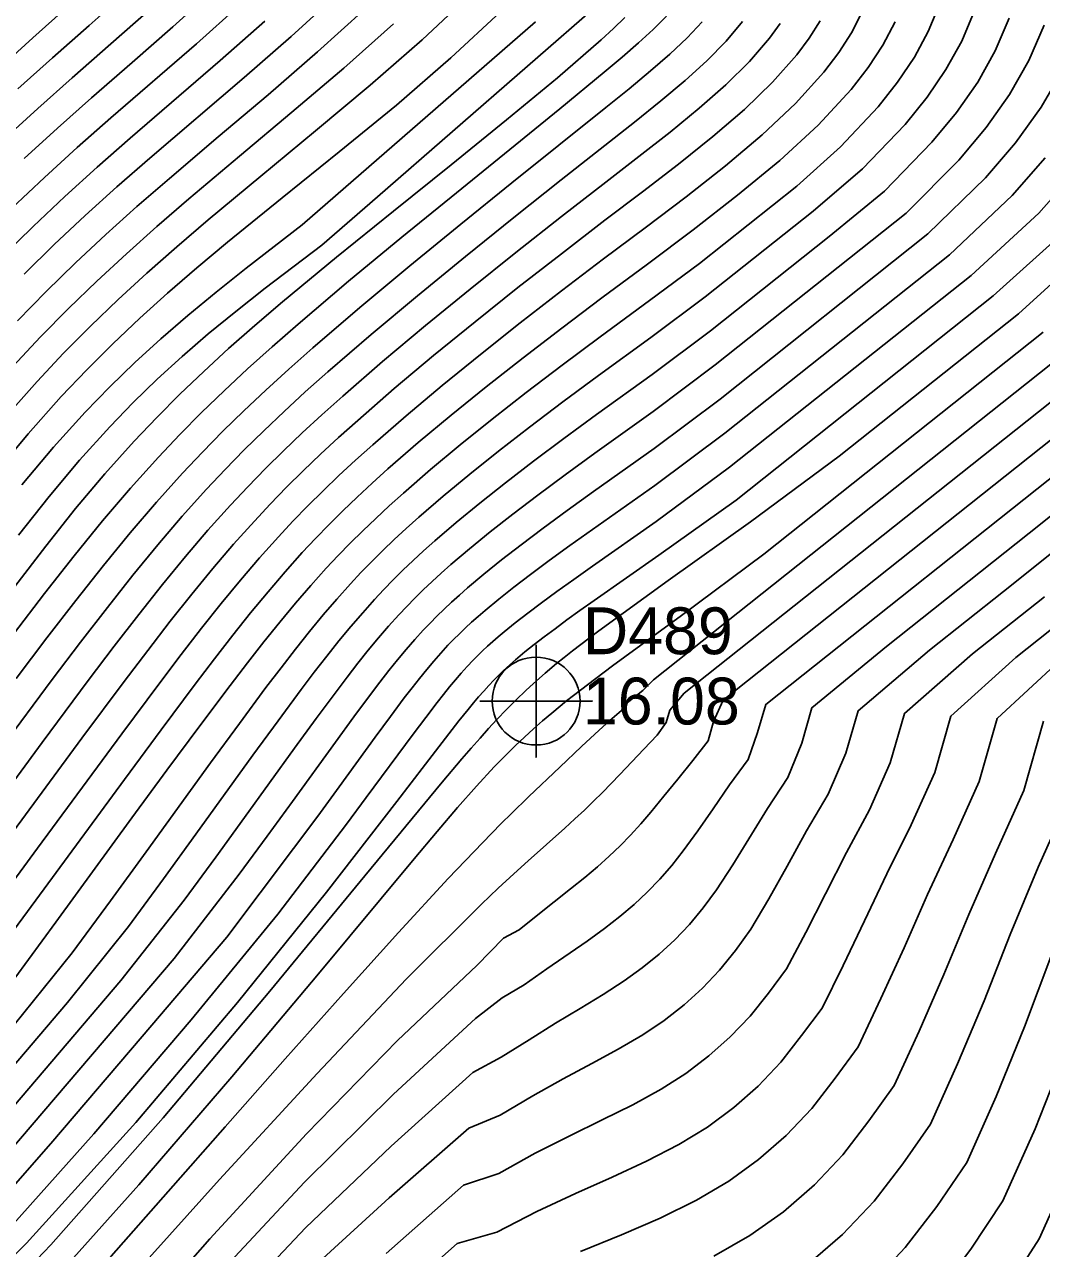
# Model space of a CAD drawing. Extents: x 2356077 to 2359823, y 225951 to 227822.
# Drawn here: x 2356793.7 to 2356848, y 226873.7 to 226939 of the extents above; entities that cross this region are included whole.
import ezdxf

# ---------------------------------------------------------------- set-up
doc = ezdxf.new("R2010")
doc.units = 0
for name, color, linetype in [('DTM Contours Major', 7, 'Continuous'), ('DTM Contours Minor', 7, 'Continuous'), ('Exist DTM Regular Point CELL', 7, 'Continuous'), ('Exist DTM Regular Point Cogo Elevation', 7, 'Continuous'), ('Exist DTM Regular Point Cogo Number', 7, 'Continuous')]:
    doc.layers.add(name, color=color, linetype=linetype)

msp = doc.modelspace()

# ---------------------------------------------------------------- linework, layer by layer
at = {"layer": 'DTM Contours Major'}
for points in [[(2356796.008, 226939.965), (2356794.163, 226938.318), (2356792.307, 226936.646)], [(2356819.099, 226939.709), (2356816.463, 226937.248), (2356813.552, 226934.723), (2356810.505, 226932.227), (2356807.458, 226929.779), (2356804.549, 226927.417), (2356802.905, 226926.041), (2356801.347, 226924.691), (2356799.86, 226923.348), (2356798.429, 226921.993), (2356797.038, 226920.607), (2356795.674, 226919.171), (2356793.902, 226917.187), (2356792.128, 226915.072)], [(2356840.15, 226939.164), (2356839.498, 226937.933), (2356838.717, 226936.738), (2356837.807, 226935.565), (2356836.043, 226933.657), (2356834.006, 226931.772), (2356831.757, 226929.917), (2356829.389, 226928.066), (2356826.949, 226926.245), (2356824.517, 226924.443), (2356822.374, 226922.831), (2356820.308, 226921.243), (2356818.334, 226919.689), (2356816.466, 226918.176), (2356814.717, 226916.713), (2356813.104, 226915.31), (2356812.265, 226914.554), (2356811.465, 226913.812), (2356810.699, 226913.077), (2356809.96, 226912.342), (2356809.241, 226911.6), (2356808.534, 226910.845), (2356807.619, 226909.823), (2356806.704, 226908.756), (2356805.778, 226907.633), (2356804.83, 226906.444), (2356803.848, 226905.179), (2356802.821, 226903.829), (2356801.004, 226901.393), (2356799.048, 226898.734), (2356794.772, 226892.901), (2356792.48, 226889.804)], [(2356806.539, 226939.206), (2356804.161, 226937.103), (2356799.36, 226932.968), (2356797.585, 226931.405), (2356795.859, 226929.84), (2356794.172, 226928.253), (2356792.515, 226926.624)], [(2356829.864, 226939.174), (2356829.058, 226938.318), (2356828.136, 226937.446), (2356827.104, 226936.546), (2356825.966, 226935.602), (2356824.728, 226934.6), (2356819.717, 226930.576), (2356816.998, 226928.38), (2356814.261, 226926.14), (2356811.598, 226923.919), (2356809.101, 226921.776), (2356807.808, 226920.632), (2356806.585, 226919.518), (2356805.418, 226918.419), (2356804.295, 226917.322), (2356803.206, 226916.213), (2356802.137, 226915.079), (2356800.748, 226913.532), (2356799.352, 226911.899), (2356797.929, 226910.16), (2356796.456, 226908.296), (2356794.913, 226906.289), (2356793.279, 226904.119)], [(2356849.089, 226936.576), (2356847.954, 226934.622), (2356846.582, 226932.721), (2356844.98, 226930.844), (2356841.902, 226927.85), (2356830.816, 226919.04), (2356827.299, 226916.396), (2356824.07, 226914.101), (2356822.661, 226913.085), (2356821.378, 226912.143), (2356820.215, 226911.268), (2356819.162, 226910.453), (2356818.211, 226909.689), (2356817.353, 226908.968), (2356816.912, 226908.582), (2356816.494, 226908.203), (2356816.095, 226907.83), (2356815.714, 226907.458), (2356815.346, 226907.085), (2356814.987, 226906.708), (2356814.528, 226906.202), (2356814.073, 226905.678), (2356813.617, 226905.129), (2356813.152, 226904.549), (2356812.673, 226903.932), (2356812.173, 226903.273), (2356811.283, 226902.074), (2356810.303, 226900.731), (2356808.009, 226897.565), (2356806.667, 226895.72), (2356805.173, 226893.685), (2356801.698, 226889.177), (2356792.882, 226878.843)], [(2356848.045, 226922.603), (2356833.152, 226910.767), (2356828.768, 226907.493), (2356825.081, 226904.806), (2356824.184, 226904.134), (2356823.371, 226903.511), (2356822.634, 226902.929), (2356821.839, 226902.281), (2356821.347, 226901.864), (2356820.864, 226901.441), (2356820.384, 226901.003), (2356819.912, 226900.556), (2356819.677, 226900.326), (2356818.773, 226899.405), (2356817.83, 226898.384), (2356816.821, 226897.243), (2356815.722, 226895.959), (2356814.505, 226894.512), (2356809.307, 226888.259), (2356804.777, 226882.869), (2356799.811, 226877.101), (2356794.662, 226871.347), (2356789.585, 226866.001)], [(2356852.128, 226915.737), (2356847.915, 226912.369), (2356839.688, 226905.831), (2356835.712, 226902.565), (2356835.174, 226900.676), (2356834.434, 226898.85), (2356833.356, 226897.194), (2356831.506, 226894.176), (2356830.633, 226892.844), (2356829.924, 226891.885), (2356829.184, 226891.001), (2356828.402, 226890.181), (2356827.567, 226889.413), (2356826.668, 226888.686), (2356825.694, 226887.988), (2356824.576, 226887.266), (2356823.361, 226886.526), (2356822.045, 226885.733), (2356820.628, 226884.848), (2356819.137, 226883.924), (2356817.636, 226883.101), (2356813.282, 226879.173), (2356808.71, 226874.817), (2356803.985, 226869.818)], [(2356848.073, 226901.855), (2356847.017, 226898.148), (2356845.511, 226894.788), (2356844.083, 226891.527), (2356842.758, 226888.337), (2356841.435, 226885.302), (2356840.111, 226882.402), (2356838.752, 226880.515), (2356837.365, 226878.717), (2356835.847, 226877.105), (2356834.197, 226875.67), (2356832.412, 226874.403), (2356830.492, 226873.294)]]:
    msp.add_lwpolyline(points, dxfattribs=at)
at = {"layer": 'DTM Contours Minor'}
for points in [[(2356817.46, 226940.6), (2356814.935, 226938.214), (2356812.156, 226935.783), (2356809.246, 226933.346), (2356806.326, 226930.94), (2356803.519, 226928.604), (2356801.844, 226927.17), (2356800.249, 226925.761), (2356798.72, 226924.356), (2356797.242, 226922.937), (2356795.803, 226921.484), (2356794.386, 226919.978), (2356792.543, 226917.899)], [(2356799.09, 226940.699), (2356797.163, 226938.976), (2356795.208, 226937.248), (2356793.365, 226935.597)], [(2356803.75, 226940.822), (2356801.629, 226938.901), (2356799.461, 226937.001), (2356797.29, 226935.11), (2356795.477, 226933.502), (2356793.69, 226931.873)], [(2356810.339, 226940.596), (2356807.942, 226938.391), (2356805.433, 226936.198), (2356800.402, 226931.894), (2356798.649, 226930.358), (2356796.953, 226928.827), (2356795.305, 226927.282), (2356793.693, 226925.705)], [(2356805.144, 226940.015), (2356802.896, 226938.003), (2356798.327, 226934.04), (2356796.532, 226932.455), (2356794.775, 226930.857), (2356793.047, 226929.228)], [(2356842.515, 226940.09), (2356841.924, 226938.656), (2356841.182, 226937.279), (2356840.289, 226935.942), (2356839.248, 226934.63), (2356837.235, 226932.492), (2356834.911, 226930.398), (2356829.729, 226926.28), (2356827.052, 226924.291), (2356824.426, 226922.364), (2356822.398, 226920.852), (2356820.474, 226919.385), (2356818.658, 226917.965), (2356816.957, 226916.595), (2356815.377, 226915.279), (2356813.924, 226914.018), (2356813.169, 226913.339), (2356812.45, 226912.672), (2356811.76, 226912.011), (2356811.094, 226911.351), (2356810.446, 226910.685), (2356809.811, 226910.008), (2356808.988, 226909.094), (2356808.165, 226908.141), (2356807.334, 226907.14), (2356806.484, 226906.082), (2356805.605, 226904.959), (2356804.687, 226903.762), (2356803.065, 226901.604), (2356801.316, 226899.239), (2356799.448, 226896.689), (2356795.378, 226891.117), (2356793.191, 226888.137)], [(2356811.869, 226939.845), (2356809.346, 226937.562), (2356806.705, 226935.281), (2356804.039, 226933.025), (2356801.441, 226930.815), (2356799.712, 226929.307), (2356798.049, 226927.813), (2356796.439, 226926.312), (2356794.872, 226924.785), (2356793.334, 226923.214)], [(2356824.551, 226940.282), (2356812.545, 226929.831), (2356809.572, 226927.246), (2356806.546, 226924.949), (2356804.988, 226923.719), (2356803.521, 226922.512), (2356802.13, 226921.311), (2356800.8, 226920.098), (2356799.517, 226918.855), (2356798.265, 226917.564), (2356796.648, 226915.772), (2356795.034, 226913.848), (2356793.398, 226911.77)], [(2356846.233, 226939.364), (2356845.496, 226937.626), (2356844.562, 226935.957), (2356843.435, 226934.337), (2356842.121, 226932.742), (2356839.581, 226930.135), (2356836.633, 226927.715), (2356830.301, 226922.682), (2356827.199, 226920.352), (2356824.234, 226918.214), (2356822.484, 226916.931), (2356820.864, 226915.718), (2356819.37, 226914.57), (2356817.997, 226913.482), (2356816.741, 226912.448), (2356815.596, 226911.465), (2356815.004, 226910.936), (2356814.441, 226910.416), (2356813.902, 226909.901), (2356813.383, 226909.388), (2356812.88, 226908.871), (2356812.389, 226908.346), (2356811.754, 226907.64), (2356811.123, 226906.905), (2356810.488, 226906.135), (2356809.84, 226905.323), (2356809.172, 226904.46), (2356808.475, 226903.539), (2356807.242, 226901.876), (2356805.9, 226900.034), (2356802.852, 226895.819), (2356801.129, 226893.445), (2356799.261, 226890.892), (2356796.006, 226886.832), (2356788.454, 226877.979)], [(2356836.152, 226939.222), (2356835.579, 226938.305), (2356834.914, 226937.406), (2356833.622, 226935.944), (2356832.115, 226934.494), (2356830.43, 226933.043), (2356828.603, 226931.581), (2356826.672, 226930.096), (2356824.674, 226928.578), (2356822.355, 226926.797), (2356820.035, 226924.984), (2356817.75, 226923.163), (2356815.539, 226921.358), (2356813.439, 226919.595), (2356811.487, 226917.899), (2356810.473, 226916.988), (2356809.508, 226916.095), (2356808.585, 226915.213), (2356807.694, 226914.331), (2356806.828, 226913.439), (2356805.977, 226912.53), (2356804.872, 226911.296), (2356803.765, 226910.001), (2356802.642, 226908.634), (2356801.487, 226907.18), (2356800.286, 226905.627), (2356799.025, 226903.962), (2356796.782, 226900.951), (2356791.835, 226894.241)], [(2356838.385, 226939.668), (2356837.821, 226938.581), (2356837.147, 226937.526), (2356836.362, 226936.491), (2356834.84, 226934.81), (2356833.073, 226933.144), (2356831.113, 226931.489), (2356829.012, 226929.837), (2356826.825, 226928.181), (2356824.601, 226926.515), (2356822.361, 226924.814), (2356820.163, 226923.11), (2356818.033, 226921.422), (2356815.994, 226919.764), (2356814.072, 226918.152), (2356812.292, 226916.604), (2356811.366, 226915.77), (2356810.485, 226914.953), (2356809.641, 226914.144), (2356808.827, 226913.335), (2356808.034, 226912.519), (2356807.256, 226911.686), (2356806.246, 226910.558), (2356805.235, 226909.377), (2356804.211, 226908.131), (2356803.16, 226906.81), (2356802.07, 226905.403), (2356800.928, 226903.897), (2356798.902, 226901.178), (2356794.417, 226895.079), (2356792.006, 226891.818)], [(2356832.008, 226939.181), (2356831.138, 226938.136), (2356830.114, 226937.093), (2356828.95, 226936.036), (2356827.659, 226934.951), (2356826.254, 226933.822), (2356822.345, 226930.74), (2356819.817, 226928.73), (2356817.237, 226926.652), (2356814.675, 226924.554), (2356812.203, 226922.484), (2356809.892, 226920.489), (2356808.694, 226919.421), (2356807.558, 226918.379), (2356806.474, 226917.351), (2356805.429, 226916.325), (2356804.414, 226915.287), (2356803.417, 226914.227), (2356802.123, 226912.783), (2356800.823, 226911.263), (2356799.5, 226909.648), (2356798.134, 226907.923), (2356796.707, 226906.071), (2356795.198, 226904.075), (2356792.503, 226900.448)], [(2356800.361, 226939.799), (2356798.314, 226937.988), (2356796.251, 226936.179), (2356794.421, 226934.55), (2356792.605, 226932.888)], [(2356827.953, 226939.467), (2356827.255, 226938.767), (2356826.471, 226938.043), (2356825.6, 226937.284), (2356824.643, 226936.476), (2356822.271, 226934.522), (2356819.604, 226932.357), (2356816.757, 226930.053), (2356813.847, 226927.683), (2356810.992, 226925.322), (2356808.306, 226923.043), (2356806.918, 226921.827), (2356805.607, 226920.645), (2356804.358, 226919.48), (2356803.158, 226918.317), (2356801.995, 226917.14), (2356800.854, 226915.934), (2356799.372, 226914.286), (2356797.882, 226912.54), (2356796.361, 226910.675), (2356794.785, 226908.668), (2356793.13, 226906.5)], [(2356844.37, 226939.729), (2356843.707, 226938.143), (2356842.87, 226936.62), (2356841.862, 226935.142), (2356840.686, 226933.688), (2356838.413, 226931.317), (2356835.778, 226929.061), (2356830.024, 226924.489), (2356827.133, 226922.326), (2356824.328, 226920.288), (2356822.432, 226918.886), (2356820.656, 226917.544), (2356819, 226916.26), (2356817.464, 226915.032), (2356816.048, 226913.859), (2356814.752, 226912.739), (2356814.08, 226912.135), (2356813.439, 226911.542), (2356812.826, 226910.954), (2356812.235, 226910.367), (2356811.661, 226909.776), (2356811.099, 226909.174), (2356810.371, 226908.363), (2356809.647, 226907.519), (2356808.916, 226906.633), (2356808.17, 226905.697), (2356807.4, 226904.704), (2356806.597, 226903.644), (2356805.178, 226901.733), (2356803.641, 226899.628), (2356800.203, 226894.881), (2356798.297, 226892.257), (2356796.261, 226889.481), (2356793.156, 226885.654)], [(2356825.735, 226939.396), (2356825.129, 226938.81), (2356824.473, 226938.212), (2356822.149, 226936.188), (2356819.435, 226933.936), (2356816.471, 226931.541), (2356813.396, 226929.072), (2356810.351, 226926.61), (2356807.481, 226924.232), (2356805.999, 226922.965), (2356804.602, 226921.731), (2356803.274, 226920.514), (2356802.001, 226919.296), (2356800.77, 226918.06), (2356799.565, 226916.79), (2356798.004, 226915.047), (2356796.439, 226913.191), (2356794.846, 226911.198), (2356793.198, 226909.045)], [(2356820.979, 226939.176), (2356808.524, 226928.333), (2356805.546, 226926.027), (2356803.94, 226924.749), (2356802.425, 226923.496), (2356800.984, 226922.247), (2356799.603, 226920.984), (2356798.265, 226919.688), (2356796.957, 226918.34), (2356795.261, 226916.469), (2356793.564, 226914.461)], [(2356848.104, 226938.994), (2356847.29, 226937.103), (2356846.257, 226935.291), (2356845.009, 226933.53), (2356843.552, 226931.794), (2356840.739, 226928.952), (2356830.563, 226920.865), (2356827.253, 226918.374), (2356824.145, 226916.149), (2356822.558, 226914.994), (2356821.102, 226913.915), (2356819.772, 226912.903), (2356818.56, 226911.952), (2356817.458, 226911.055), (2356816.46, 226910.206), (2356815.945, 226909.749), (2356815.456, 226909.301), (2356814.989, 226908.858), (2356814.541, 226908.417), (2356814.107, 226907.973), (2356813.684, 226907.524), (2356813.139, 226906.92), (2356812.599, 226906.293), (2356812.055, 226905.635), (2356811.502, 226904.942), (2356810.931, 226904.205), (2356810.335, 226903.418), (2356809.279, 226901.993), (2356808.122, 226900.405), (2356805.455, 226896.717), (2356803.919, 226894.601), (2356802.232, 226892.296), (2356798.855, 226888.008), (2356790.661, 226878.403)], [(2356834.016, 226939.072), (2356833.462, 226938.304), (2356832.389, 226937.056), (2356831.131, 226935.813), (2356829.711, 226934.562), (2356828.155, 226933.289), (2356826.485, 226931.98), (2356824.726, 226930.622), (2356822.352, 226928.776), (2356819.921, 226926.86), (2356817.486, 226924.908), (2356815.1, 226922.957), (2356812.816, 226921.04), (2356810.687, 226919.195), (2356809.582, 226918.205), (2356808.533, 226917.238), (2356807.529, 226916.282), (2356806.562, 226915.327), (2356805.621, 226914.362), (2356804.697, 226913.377), (2356803.498, 226912.038), (2356802.295, 226910.63), (2356801.072, 226909.139), (2356799.812, 226907.551), (2356798.498, 226905.85), (2356797.115, 226904.021), (2356794.649, 226900.708), (2356792.002, 226897.121)], [(2356813.402, 226939.062), (2356810.751, 226936.703), (2356807.976, 226934.34), (2356805.184, 226932.003), (2356802.481, 226929.723), (2356800.778, 226928.249), (2356799.148, 226926.793), (2356797.578, 226925.338), (2356796.056, 226923.864), (2356794.567, 226922.351), (2356793.099, 226920.78)], [(2356848.156, 226931.912), (2356846.404, 226929.895), (2356843.058, 226926.743), (2356831.065, 226917.212), (2356827.346, 226914.432), (2356824.019, 226912.084), (2356822.806, 226911.217), (2356821.706, 226910.418), (2356820.713, 226909.682), (2356819.818, 226908.999), (2356819.013, 226908.362), (2356818.289, 226907.764), (2356817.917, 226907.444), (2356817.565, 226907.131), (2356817.231, 226906.823), (2356816.911, 226906.517), (2356816.603, 226906.21), (2356816.304, 226905.9), (2356815.922, 226905.486), (2356815.545, 226905.057), (2356815.168, 226904.608), (2356814.784, 226904.133), (2356814.388, 226903.628), (2356813.975, 226903.088), (2356813.239, 226902.103), (2356812.424, 226900.992), (2356810.497, 226898.346), (2356809.355, 226896.785), (2356808.073, 226895.048), (2356804.513, 226890.332), (2356799.995, 226885.017), (2356795.128, 226879.312), (2356790.232, 226873.745)], [(2356849.731, 226931.107), (2356847.83, 226928.954), (2356844.213, 226925.635), (2356831.329, 226915.396), (2356827.412, 226912.507), (2356824.015, 226910.125), (2356823.017, 226909.418), (2356822.113, 226908.769), (2356821.295, 226908.17), (2356820.557, 226907.615), (2356819.892, 226907.099), (2356819.293, 226906.613), (2356818.985, 226906.353), (2356818.692, 226906.099), (2356818.414, 226905.849), (2356818.148, 226905.6), (2356817.892, 226905.351), (2356817.643, 226905.101), (2356817.326, 226904.766), (2356817.013, 226904.42), (2356816.701, 226904.059), (2356816.385, 226903.677), (2356816.06, 226903.272), (2356815.722, 226902.839), (2356815.12, 226902.05), (2356814.456, 226901.16), (2356811.949, 226897.769), (2356810.898, 226896.36), (2356807.237, 226891.557), (2356802.611, 226885.92), (2356797.421, 226879.837), (2356792.073, 226873.862)], [(2356849.274, 226928.047), (2356845.385, 226924.54), (2356831.683, 226913.651), (2356827.559, 226910.705), (2356824.104, 226908.287), (2356823.345, 226907.749), (2356822.65, 226907.25), (2356822.014, 226906.785), (2356821.431, 226906.349), (2356820.898, 226905.938), (2356820.41, 226905.547), (2356819.911, 226905.127), (2356819.451, 226904.717), (2356819.232, 226904.512), (2356819.019, 226904.306), (2356818.746, 226904.031), (2356818.477, 226903.748), (2356818.209, 226903.455), (2356817.939, 226903.148), (2356817.663, 226902.824), (2356817.379, 226902.481), (2356816.881, 226901.864), (2356816.343, 226901.177), (2356815.101, 226899.562), (2356813.579, 226897.57), (2356809.82, 226892.732), (2356805.084, 226886.844), (2356799.658, 226880.426), (2356793.829, 226873.996), (2356787.884, 226868.072)], [(2356850.871, 226927.334), (2356846.744, 226923.595), (2356837.167, 226915.984), (2356832.437, 226912.483), (2356828.05, 226909.361), (2356824.353, 226906.678), (2356823.39, 226905.948), (2356822.941, 226905.598), (2356822.511, 226905.256), (2356822.098, 226904.921), (2356821.485, 226904.406), (2356820.861, 226903.857), (2356820.46, 226903.487), (2356819.942, 226902.991), (2356819.428, 226902.475), (2356818.908, 226901.931), (2356818.468, 226901.454), (2356818.014, 226900.95), (2356817.543, 226900.415), (2356817.051, 226899.846), (2356815.993, 226898.598), (2356811.861, 226893.596), (2356806.793, 226887.439), (2356801.105, 226880.688), (2356795.112, 226873.903), (2356789.133, 226867.643)], [(2356849.755, 226921.935), (2356827.267, 226904.064), (2356826.691, 226903.493), (2356825.703, 226902.713), (2356825.556, 226902.425), (2356824.94, 226901.879), (2356824.369, 226901.362), (2356823.427, 226900.494), (2356822.264, 226899.404), (2356820.616, 226897.834), (2356819.67, 226896.912), (2356819.161, 226896.406), (2356818.624, 226895.862), (2356816.323, 226893.453), (2356813.662, 226890.566), (2356810.73, 226887.318), (2356807.617, 226883.825), (2356804.411, 226880.2), (2356798.33, 226873.306), (2356795.536, 226870.162), (2356792.827, 226867.155)], [(2356851.335, 226921.165), (2356828.908, 226903.342), (2356828.138, 226902.442), (2356827.949, 226901.779), (2356827.463, 226901.11), (2356826.749, 226900.364), (2356825.478, 226899.01), (2356825.006, 226898.518), (2356824.539, 226898.043), (2356824.067, 226897.575), (2356823.583, 226897.108), (2356823.077, 226896.634), (2356822.542, 226896.143), (2356820.577, 226894.39), (2356819.813, 226893.699), (2356818.985, 226892.935), (2356818.088, 226892.087), (2356814.079, 226888.076), (2356809.32, 226883.055), (2356804.119, 226877.39), (2356798.784, 226871.446), (2356793.623, 226865.589)], [(2356852.94, 226920.415), (2356830.99, 226902.971), (2356830.476, 226901.827), (2356830.182, 226900.797), (2356829.359, 226899.754), (2356828.559, 226898.764), (2356827.826, 226897.843), (2356827.132, 226896.992), (2356826.592, 226896.365), (2356826.047, 226895.771), (2356825.487, 226895.199), (2356824.9, 226894.639), (2356824.277, 226894.081), (2356823.607, 226893.514), (2356822.839, 226892.895), (2356821.089, 226891.515), (2356820.096, 226890.717), (2356819.262, 226890.267), (2356817.848, 226888.805), (2356813.618, 226884.811), (2356808.761, 226879.831), (2356803.598, 226874.226), (2356798.449, 226868.355), (2356793.633, 226862.579)], [(2356850.307, 226916.296), (2356833.252, 226902.742), (2356832.821, 226901.239), (2356832.318, 226899.797), (2356831.327, 226898.447), (2356830.446, 226897.181), (2356829.636, 226896.005), (2356828.856, 226894.926), (2356828.237, 226894.142), (2356827.601, 226893.411), (2356826.936, 226892.722), (2356826.233, 226892.063), (2356825.478, 226891.423), (2356824.662, 226890.79), (2356823.724, 226890.115), (2356821.585, 226888.641), (2356820.376, 226887.786), (2356819.195, 226887.095), (2356817.777, 226885.976), (2356813.404, 226881.94), (2356808.658, 226877.251), (2356803.696, 226871.932)], [(2356849.929, 226911.96), (2356845.942, 226908.775), (2356841.987, 226905.632), (2356838.179, 226902.407), (2356837.533, 226900.138), (2356836.593, 226897.961), (2356835.436, 226895.991), (2356834.401, 226894.115), (2356833.426, 226892.362), (2356832.452, 226890.758), (2356831.645, 226889.608), (2356830.79, 226888.557), (2356829.877, 226887.594), (2356828.897, 226886.706), (2356827.84, 226885.883), (2356826.695, 226885.114), (2356825.386, 226884.344), (2356823.971, 226883.575), (2356822.45, 226882.762), (2356820.825, 226881.861), (2356819.096, 226880.825), (2356817.41, 226880.13), (2356813.164, 226876.408), (2356808.798, 226872.411)], [(2356848.126, 226908.485), (2356844.291, 226905.437), (2356840.651, 226902.262), (2356839.898, 226899.621), (2356838.788, 226897.123), (2356837.557, 226894.834), (2356836.448, 226892.64), (2356835.389, 226890.579), (2356834.357, 226888.638), (2356833.396, 226887.343), (2356832.417, 226886.115), (2356831.363, 226884.999), (2356830.227, 226883.983), (2356828.999, 226883.057), (2356827.673, 226882.209), (2356826.161, 226881.38), (2356824.534, 226880.572), (2356822.8, 226879.729), (2356820.962, 226878.797), (2356819.025, 226877.721), (2356817.127, 226877.094), (2356813.004, 226873.435)], [(2356850.311, 226908.195), (2356846.598, 226905.245), (2356843.124, 226902.124), (2356842.268, 226899.119), (2356841.009, 226896.32), (2356839.709, 226893.709), (2356838.528, 226891.187), (2356837.382, 226888.809), (2356836.271, 226886.54), (2356835.166, 226885.069), (2356834.056, 226883.656), (2356832.853, 226882.379), (2356831.551, 226881.227), (2356830.144, 226880.19), (2356828.626, 226879.258), (2356826.902, 226878.368), (2356825.057, 226877.519), (2356823.104, 226876.647), (2356821.053, 226875.69), (2356818.916, 226874.584), (2356816.792, 226873.97), (2356812.848, 226870.465)], [(2356848.904, 226905.052), (2356845.599, 226901.989), (2356844.641, 226898.629), (2356843.251, 226895.543), (2356841.886, 226892.608), (2356840.633, 226889.754), (2356839.399, 226887.05), (2356838.186, 226884.467), (2356836.953, 226882.792), (2356835.706, 226881.189), (2356834.348, 226879.747), (2356832.875, 226878.455), (2356831.282, 226877.304), (2356829.565, 226876.285), (2356827.621, 226875.331), (2356825.553, 226874.442), (2356823.379, 226873.544)], [(2356849.396, 226897.676), (2356847.784, 226894.052), (2356846.296, 226890.464), (2356844.901, 226886.933), (2356843.486, 226883.562), (2356842.042, 226880.344), (2356840.561, 226878.236), (2356839.03, 226876.24), (2356837.349, 226874.456), (2356835.518, 226872.875)], [(2356848.524, 226889.415), (2356847.057, 226885.541), (2356845.549, 226881.828), (2356843.975, 226878.296), (2356842.377, 226875.957), (2356840.7, 226873.76), (2356838.853, 226871.801), (2356836.837, 226870.072), (2356834.657, 226868.566), (2356832.314, 226867.275), (2356829.678, 226866.123), (2356826.911, 226865.111), (2356824.061, 226864.144), (2356821.173, 226863.132), (2356818.296, 226861.983), (2356815.384, 226861.047), (2356812.386, 226858.674), (2356809.458, 226856.393), (2356806.72, 226853.828), (2356804.198, 226851.044), (2356801.922, 226848.107), (2356799.917, 226845.083), (2356798.451, 226842.509), (2356797.188, 226839.941)], [(2356849.225, 226884.157), (2356847.622, 226880.1), (2356845.907, 226876.258), (2356844.199, 226873.676), (2356842.374, 226871.276), (2356840.357, 226869.141), (2356838.155, 226867.263), (2356835.771, 226865.635), (2356833.211, 226864.249), (2356830.334, 226863.029), (2356827.326, 226861.973), (2356824.246, 226860.986), (2356821.155, 226859.971), (2356818.111, 226858.831), (2356815.062, 226857.823), (2356812.324, 226855.766), (2356809.665, 226853.777), (2356807.212, 226851.554), (2356804.981, 226849.148), (2356802.987, 226846.611), (2356801.243, 226843.992), (2356799.975, 226841.753), (2356798.886, 226839.506)], [(2356849.703, 226878.377), (2356847.841, 226874.227), (2356846.025, 226871.395), (2356844.05, 226868.79), (2356841.863, 226866.477), (2356839.472, 226864.448), (2356836.881, 226862.696), (2356834.099, 226861.215), (2356830.977, 226859.923), (2356827.723, 226858.824), (2356824.412, 226857.818), (2356821.119, 226856.804), (2356817.917, 226855.683), (2356814.768, 226854.604), (2356812.289, 226852.88), (2356809.906, 226851.182), (2356807.738, 226849.296), (2356805.79, 226847.261), (2356804.067, 226845.112), (2356802.575, 226842.887), (2356801.496, 226840.974)]]:
    msp.add_lwpolyline(points, dxfattribs=at)
at = {"layer": 'Exist DTM Regular Point CELL'}
msp.add_lwpolyline([(2356821.003, 226905.923), (2356821.003, 226899.923), (2356821.003, 226902.923), (2356824.003, 226902.923), (2356818.003, 226902.923)], dxfattribs=at)
msp.add_circle((2356821.003, 226902.923), 2.344, dxfattribs=at)

# ---------------------------------------------------------------- texts
at = {"layer": 'Exist DTM Regular Point Cogo Elevation'}
msp.add_text('16.08', height=2.5, dxfattribs=at).set_placement((2356823.503, 226901.673))
at = {"layer": 'Exist DTM Regular Point Cogo Number'}
msp.add_text('D489', height=2.5, dxfattribs=at).set_placement((2356823.503, 226905.423))

doc.saveas('drawing.dxf')
